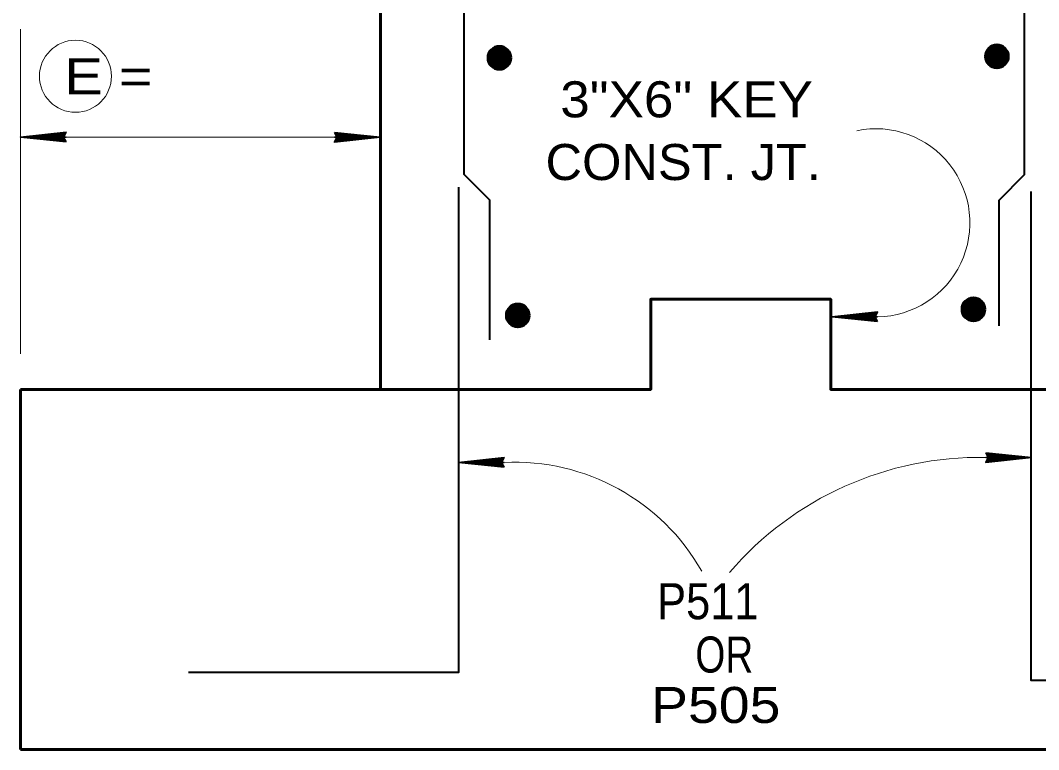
# Model space of a CAD drawing. Extents: x 6.34 to 9.53, y -1.46 to 0.53.
# Drawn here: x 7.7101 to 7.9457, y -0.8062 to -0.6375 of the extents above; entities that cross this region are included whole.
import ezdxf

# ---------------------------------------------------------------- set-up
doc = ezdxf.new("R2010")
doc.units = 0
doc.header["$LTSCALE"] = 0.0033
doc.layers.add('1', color=7, linetype='Continuous', lineweight=40)

msp = doc.modelspace()

# ---------------------------------------------------------------- linework, layer by layer
at = {"layer": '1', "lineweight": 13}
for p, q in [((7.710083, -0.714583), (7.710083, -0.6395)), ((7.710083, -0.6645), (7.7915, -0.6645))]:
    msp.add_line(p, q, dxfattribs=at)
at = {"layer": '1'}
for p, q in [((7.818833, -0.644583), (7.823417, -0.64675)), ((7.819083, -0.645), (7.823, -0.64575)), ((7.819083, -0.645167), (7.823, -0.645917)), ((7.819083, -0.645417), (7.822917, -0.646167)), ((7.819167, -0.644583), (7.823083, -0.64525)), ((7.819167, -0.64475), (7.823083, -0.6455)), ((7.81925, -0.64425), (7.823083, -0.644917)), ((7.821167, -0.645083), (7.8225, -0.644083)), ((7.82325, -0.644917), (7.822, -0.64375)), ((7.933917, -0.64425), (7.9385, -0.646417)), ((7.934083, -0.64525), (7.937917, -0.645917)), ((7.934083, -0.645417), (7.937917, -0.646167)), ((7.934167, -0.644667), (7.938083, -0.645417)), ((7.934167, -0.644833), (7.938083, -0.645583)), ((7.934167, -0.645083), (7.938, -0.645833)), ((7.93425, -0.64425), (7.938167, -0.644917)), ((7.93425, -0.644417), (7.938167, -0.645167)), ((7.934333, -0.643917), (7.938167, -0.644583)), ((7.93625, -0.64475), (7.937583, -0.64375)), ((7.938333, -0.644583), (7.937083, -0.643417)), ((7.818667, -0.647333), (7.8225, -0.648083)), ((7.818667, -0.6475), (7.8225, -0.64825)), ((7.81875, -0.646833), (7.822667, -0.647583)), ((7.81875, -0.647), (7.822583, -0.64775)), ((7.81875, -0.64725), (7.822583, -0.647917)), ((7.818833, -0.646417), (7.82275, -0.647167)), ((7.818917, -0.646), (7.82275, -0.64675)), ((7.818917, -0.646167), (7.82275, -0.646917)), ((7.819, -0.645583), (7.822833, -0.64625)), ((7.819, -0.64575), (7.822833, -0.6465)), ((7.823, -0.64775), (7.81925, -0.648167)), ((7.93375, -0.647), (7.937583, -0.64775)), ((7.93375, -0.647167), (7.937583, -0.647917)), ((7.933833, -0.6465), (7.93775, -0.64725)), ((7.933833, -0.646667), (7.937667, -0.647417)), ((7.933833, -0.646917), (7.937667, -0.647583)), ((7.933917, -0.646083), (7.937833, -0.646833)), ((7.934, -0.645667), (7.937833, -0.646417)), ((7.934, -0.645833), (7.937833, -0.646583)), ((7.938083, -0.647417), (7.934333, -0.647833)), ((7.932917, -0.703083), (7.931667, -0.701917)), ((7.823083, -0.704167), (7.827667, -0.706333)), ((7.823417, -0.704167), (7.827333, -0.704833)), ((7.823417, -0.704333), (7.827333, -0.705083)), ((7.8235, -0.703833), (7.827333, -0.7045)), ((7.825417, -0.704667), (7.82675, -0.703667)), ((7.8275, -0.7045), (7.82625, -0.703333)), ((7.9285, -0.70275), (7.933083, -0.704917)), ((7.928583, -0.704167), (7.932417, -0.704917)), ((7.928583, -0.704333), (7.932417, -0.705083)), ((7.928667, -0.70375), (7.9325, -0.704417)), ((7.928667, -0.703917), (7.9325, -0.704667)), ((7.92875, -0.703167), (7.932667, -0.703917)), ((7.92875, -0.703333), (7.932667, -0.704083)), ((7.92875, -0.703583), (7.932583, -0.704333)), ((7.928833, -0.70275), (7.93275, -0.703417)), ((7.928833, -0.702917), (7.93275, -0.703667)), ((7.928917, -0.702417), (7.93275, -0.703083)), ((7.930833, -0.70325), (7.932167, -0.70225)), ((7.823, -0.706417), (7.826917, -0.707167)), ((7.823, -0.706583), (7.826833, -0.707333)), ((7.823083, -0.706), (7.827, -0.70675)), ((7.823167, -0.705583), (7.827, -0.706333)), ((7.823167, -0.70575), (7.827, -0.7065)), ((7.82325, -0.705167), (7.827083, -0.705833)), ((7.82325, -0.705333), (7.827083, -0.706083)), ((7.823333, -0.704583), (7.82725, -0.705333)), ((7.823333, -0.70475), (7.82725, -0.7055)), ((7.823333, -0.705), (7.827167, -0.70575)), ((7.928333, -0.7055), (7.932167, -0.70625)), ((7.928333, -0.705667), (7.932167, -0.706417)), ((7.928417, -0.705), (7.932333, -0.70575)), ((7.928417, -0.705167), (7.93225, -0.705917)), ((7.928417, -0.705417), (7.93225, -0.706083)), ((7.9285, -0.704583), (7.932417, -0.705333)), ((7.932667, -0.705917), (7.928917, -0.706333)), ((7.822917, -0.706917), (7.82675, -0.707667)), ((7.822917, -0.707083), (7.82675, -0.707833)), ((7.823, -0.706833), (7.826833, -0.7075)), ((7.82725, -0.707333), (7.8235, -0.70775))]:
    msp.add_line(p, q, dxfattribs=at)
at = {"layer": '1', "lineweight": 60}
for p, q in [((7.819083, -0.644583), (7.818917, -0.6475)), ((7.819333, -0.644583), (7.819083, -0.6475)), ((7.8195, -0.644583), (7.819333, -0.647583)), ((7.819667, -0.644583), (7.819417, -0.647583)), ((7.819833, -0.644583), (7.819667, -0.647583)), ((7.820083, -0.644583), (7.819917, -0.647583)), ((7.820333, -0.644583), (7.820083, -0.647583)), ((7.820417, -0.644667), (7.82025, -0.647583)), ((7.820583, -0.644667), (7.820417, -0.647583)), ((7.82075, -0.644667), (7.820583, -0.647583)), ((7.821, -0.644667), (7.82075, -0.647583)), ((7.821167, -0.644667), (7.821, -0.647583)), ((7.821417, -0.64475), (7.821167, -0.647667)), ((7.821667, -0.64475), (7.821417, -0.647667)), ((7.821833, -0.64475), (7.821667, -0.647667)), ((7.821917, -0.64475), (7.82175, -0.647667)), ((7.822083, -0.64475), (7.821917, -0.647667)), ((7.822167, -0.64475), (7.822, -0.647667)), ((7.822417, -0.644833), (7.822167, -0.64775)), ((7.822583, -0.644833), (7.822417, -0.64775)), ((7.82275, -0.644833), (7.8225, -0.64775)), ((7.822917, -0.644833), (7.82275, -0.64775)), ((7.823167, -0.644833), (7.823, -0.64775)), ((7.823417, -0.64675), (7.82325, -0.644917)), ((7.934167, -0.64425), (7.934, -0.647167)), ((7.934417, -0.64425), (7.934167, -0.647167)), ((7.934583, -0.64425), (7.934417, -0.64725)), ((7.93475, -0.64425), (7.9345, -0.64725)), ((7.934917, -0.64425), (7.93475, -0.64725)), ((7.935167, -0.64425), (7.935, -0.64725)), ((7.935417, -0.64425), (7.935167, -0.64725)), ((7.9355, -0.644333), (7.935333, -0.64725)), ((7.935667, -0.644333), (7.9355, -0.64725)), ((7.935833, -0.644333), (7.935667, -0.64725)), ((7.936083, -0.644333), (7.935833, -0.64725)), ((7.93625, -0.644333), (7.936083, -0.64725)), ((7.9365, -0.644417), (7.93625, -0.647333)), ((7.93675, -0.644417), (7.9365, -0.647333)), ((7.936917, -0.644417), (7.93675, -0.647333)), ((7.937, -0.644417), (7.936833, -0.647333)), ((7.937167, -0.644417), (7.937, -0.647333)), ((7.93725, -0.644417), (7.937083, -0.647333)), ((7.9375, -0.6445), (7.93725, -0.647417)), ((7.937667, -0.6445), (7.9375, -0.647417)), ((7.937833, -0.6445), (7.937583, -0.647417)), ((7.938, -0.6445), (7.937833, -0.647417)), ((7.93825, -0.6445), (7.938083, -0.647417)), ((7.9385, -0.646417), (7.938333, -0.644583)), ((7.823417, -0.64675), (7.818667, -0.6475)), ((7.9385, -0.646417), (7.93375, -0.647167)), ((7.823333, -0.704167), (7.823167, -0.707083)), ((7.823583, -0.704167), (7.823333, -0.707083)), ((7.82375, -0.704167), (7.823583, -0.707167)), ((7.823917, -0.704167), (7.823667, -0.707167)), ((7.824083, -0.704167), (7.823917, -0.707167)), ((7.824333, -0.704167), (7.824167, -0.707167)), ((7.824583, -0.704167), (7.824333, -0.707167)), ((7.824667, -0.70425), (7.8245, -0.707167)), ((7.824833, -0.70425), (7.824667, -0.707167)), ((7.825, -0.70425), (7.824833, -0.707167)), ((7.82525, -0.70425), (7.825, -0.707167)), ((7.825417, -0.70425), (7.82525, -0.707167)), ((7.825667, -0.704333), (7.825417, -0.70725)), ((7.825917, -0.704333), (7.825667, -0.70725)), ((7.826083, -0.704333), (7.825917, -0.70725)), ((7.826167, -0.704333), (7.826, -0.70725)), ((7.826333, -0.704333), (7.826167, -0.70725)), ((7.826417, -0.704333), (7.82625, -0.70725)), ((7.92875, -0.70275), (7.928583, -0.705667)), ((7.929, -0.70275), (7.92875, -0.705667)), ((7.929167, -0.70275), (7.929, -0.70575)), ((7.929333, -0.70275), (7.929083, -0.70575)), ((7.9295, -0.70275), (7.929333, -0.70575)), ((7.92975, -0.70275), (7.929583, -0.70575)), ((7.93, -0.70275), (7.92975, -0.70575)), ((7.930083, -0.702833), (7.929917, -0.70575)), ((7.93025, -0.702833), (7.930083, -0.70575)), ((7.930417, -0.702833), (7.93025, -0.70575)), ((7.930667, -0.702833), (7.930417, -0.70575)), ((7.930833, -0.702833), (7.930667, -0.70575)), ((7.931083, -0.702917), (7.930833, -0.705833)), ((7.931333, -0.702917), (7.931083, -0.705833)), ((7.9315, -0.702917), (7.931333, -0.705833)), ((7.931583, -0.702917), (7.931417, -0.705833)), ((7.93175, -0.702917), (7.931583, -0.705833)), ((7.931833, -0.702917), (7.931667, -0.705833)), ((7.932083, -0.703), (7.931833, -0.705917)), ((7.93225, -0.703), (7.932083, -0.705917)), ((7.932417, -0.703), (7.932167, -0.705917)), ((7.932583, -0.703), (7.932417, -0.705917)), ((7.932833, -0.703), (7.932667, -0.705917)), ((7.933083, -0.704917), (7.932917, -0.703083)), ((7.827667, -0.706333), (7.822917, -0.707083)), ((7.826667, -0.704417), (7.826417, -0.707333)), ((7.826833, -0.704417), (7.826667, -0.707333)), ((7.827, -0.704417), (7.82675, -0.707333)), ((7.827167, -0.704417), (7.827, -0.707333)), ((7.827417, -0.704417), (7.82725, -0.707333)), ((7.827667, -0.706333), (7.8275, -0.7045)), ((7.933083, -0.704917), (7.928333, -0.705667)), ((7.710083, -0.806167), (7.710083, -0.722833)), ((8.043417, -0.806167), (7.710083, -0.806167))]:
    msp.add_line(p, q, dxfattribs=at)
at = {"layer": '1', "lineweight": 35}
for p, q in [((7.720417, -0.665333), (7.712583, -0.664333)), ((7.720417, -0.663417), (7.713083, -0.66425)), ((7.720417, -0.663583), (7.713083, -0.664333)), ((7.720417, -0.663667), (7.713083, -0.6645)), ((7.7205, -0.663833), (7.713167, -0.664583)), ((7.783, -0.6635), (7.790833, -0.664417)), ((7.783, -0.6635), (7.790833, -0.664417)), ((7.783, -0.663583), (7.790833, -0.664417)), ((7.783, -0.663667), (7.790833, -0.6645)), ((7.783, -0.663667), (7.790833, -0.664667)), ((7.720667, -0.6645), (7.710083, -0.6645)), ((7.720417, -0.665333), (7.712583, -0.6645)), ((7.720417, -0.6655), (7.712583, -0.664583)), ((7.720417, -0.6655), (7.712583, -0.664583)), ((7.720417, -0.665417), (7.712583, -0.664583)), ((7.78275, -0.6645), (7.793333, -0.6645)), ((7.782917, -0.665167), (7.79025, -0.664417)), ((7.783, -0.665333), (7.790333, -0.6645)), ((7.783, -0.665417), (7.790333, -0.664667)), ((7.783, -0.665583), (7.790333, -0.66475)), ((7.908417, -0.706083), (7.897833, -0.706083)), ((7.908167, -0.706917), (7.900333, -0.705917)), ((7.908167, -0.706917), (7.900333, -0.706083)), ((7.908167, -0.707083), (7.900333, -0.706167)), ((7.908167, -0.707083), (7.900333, -0.706167)), ((7.908167, -0.707), (7.900333, -0.706167)), ((7.908167, -0.705), (7.900833, -0.705833)), ((7.908167, -0.705167), (7.900833, -0.705917)), ((7.908167, -0.70525), (7.900833, -0.706083)), ((7.90825, -0.705417), (7.900917, -0.706167)), ((7.82175, -0.740583), (7.813917, -0.739583)), ((7.82175, -0.738667), (7.814417, -0.7395)), ((7.82175, -0.738833), (7.814417, -0.739583)), ((7.82175, -0.738917), (7.814417, -0.73975)), ((7.821833, -0.739083), (7.8145, -0.739833)), ((7.933417, -0.738583), (7.944, -0.738583)), ((7.933583, -0.73925), (7.940917, -0.7385)), ((7.933667, -0.737583), (7.9415, -0.7385)), ((7.933667, -0.737583), (7.9415, -0.7385)), ((7.933667, -0.737667), (7.9415, -0.7385)), ((7.933667, -0.73775), (7.9415, -0.738583)), ((7.933667, -0.73775), (7.9415, -0.73875)), ((7.933667, -0.739417), (7.941, -0.738583)), ((7.933667, -0.7395), (7.941, -0.73875)), ((7.933667, -0.739667), (7.941, -0.738833)), ((7.822, -0.73975), (7.811417, -0.73975)), ((7.82175, -0.740583), (7.813917, -0.73975)), ((7.82175, -0.74075), (7.813917, -0.739833)), ((7.82175, -0.74075), (7.813917, -0.739833)), ((7.82175, -0.740667), (7.813917, -0.739833))]:
    msp.add_line(p, q, dxfattribs=at)
at = {"layer": '1', "lineweight": 60}
for points in [[(7.710083, -0.722833), (7.793417, -0.722833), (7.793417, -0.3895), (7.960083, -0.3895), (7.960083, -0.722833), (8.043417, -0.722833)], [(7.81825, -0.64625), (7.823417, -0.645583), (7.818833, -0.644583)], [(7.8225, -0.64825), (7.8225, -0.644083), (7.820833, -0.64875), (7.821333, -0.643583), (7.81925, -0.648167), (7.82, -0.643667), (7.821583, -0.648667), (7.818417, -0.645333), (7.82325, -0.644917), (7.82, -0.648583), (7.822, -0.64375), (7.818833, -0.644583), (7.818667, -0.6475)], [(7.81925, -0.648167), (7.82075, -0.645917), (7.818583, -0.645), (7.820583, -0.643583), (7.82075, -0.645833), (7.822417, -0.648167), (7.818417, -0.645833), (7.821167, -0.645083)], [(7.822, -0.64375), (7.82075, -0.645917), (7.823, -0.64775)], [(7.933333, -0.645917), (7.9385, -0.64525), (7.933917, -0.64425)], [(7.937583, -0.647917), (7.937583, -0.64375), (7.935917, -0.648417), (7.936417, -0.64325), (7.934333, -0.647833), (7.935083, -0.643333), (7.936667, -0.648333), (7.9335, -0.645), (7.938333, -0.644583), (7.935083, -0.64825), (7.937083, -0.643417), (7.933917, -0.64425), (7.93375, -0.647167)], [(7.934333, -0.647833), (7.935833, -0.645583), (7.933667, -0.644667), (7.935667, -0.64325), (7.935833, -0.6455), (7.9375, -0.647833), (7.9335, -0.6455), (7.93625, -0.64475)], [(7.937083, -0.643417), (7.935833, -0.645583), (7.938083, -0.647417)], [(7.793417, -0.722833), (7.855917, -0.722833), (7.855917, -0.702), (7.897583, -0.702), (7.897583, -0.722833), (7.960083, -0.722833)], [(7.932167, -0.706417), (7.932167, -0.70225), (7.9305, -0.706917), (7.931, -0.70175), (7.928917, -0.706333), (7.929667, -0.701833), (7.93125, -0.706833), (7.928083, -0.7035), (7.932917, -0.703083), (7.929667, -0.70675), (7.931667, -0.701917), (7.9285, -0.70275), (7.928333, -0.705667)], [(7.928917, -0.706333), (7.930417, -0.704083), (7.92825, -0.703167), (7.93025, -0.70175), (7.930417, -0.704), (7.932083, -0.706333), (7.928083, -0.704), (7.930833, -0.70325)], [(7.931667, -0.701917), (7.930417, -0.704083), (7.932667, -0.705917)], [(7.8225, -0.705833), (7.827667, -0.705167), (7.823083, -0.704167)], [(7.82675, -0.707833), (7.82675, -0.703667), (7.825083, -0.708333), (7.825583, -0.703167), (7.8235, -0.70775), (7.82425, -0.70325), (7.825833, -0.70825), (7.822667, -0.704917), (7.8275, -0.7045), (7.82425, -0.708167), (7.82625, -0.703333), (7.823083, -0.704167), (7.822917, -0.707083)], [(7.8235, -0.70775), (7.825, -0.7055), (7.822833, -0.704583), (7.824833, -0.703167), (7.825, -0.705417), (7.826667, -0.70775), (7.822667, -0.705417), (7.825417, -0.704667)], [(7.82625, -0.703333), (7.825, -0.7055), (7.82725, -0.707333)], [(7.927917, -0.704417), (7.933083, -0.70375), (7.9285, -0.70275)]]:
    msp.add_lwpolyline(points, dxfattribs=at)
at = {"layer": '1'}
for points in [[(7.818583, -0.410167), (7.818583, -0.458833), (7.812667, -0.46475), (7.812667, -0.673083), (7.818583, -0.679), (7.818583, -0.711417)], [(7.9365, -0.708167), (7.9365, -0.679083), (7.942417, -0.673167), (7.942417, -0.464833), (7.9365, -0.458917), (7.9365, -0.410333)], [(7.818667, -0.6475), (7.82075, -0.64875), (7.8225, -0.64825), (7.823417, -0.64675)], [(7.93375, -0.647167), (7.935833, -0.648417), (7.937583, -0.647917), (7.9385, -0.646417)], [(7.749, -0.78825), (7.8115, -0.78825), (7.8115, -0.676083)], [(7.943833, -0.677083), (7.943833, -0.790083), (8.006333, -0.790083)], [(7.822917, -0.707083), (7.825, -0.708333), (7.82675, -0.707833), (7.827667, -0.706333)], [(7.928333, -0.705667), (7.930417, -0.706917), (7.932167, -0.706417), (7.933083, -0.704917)]]:
    msp.add_lwpolyline(points, dxfattribs=at)
at = {"layer": '1', "lineweight": 35}
for points in [[(7.720667, -0.665583), (7.710083, -0.6645), (7.720667, -0.663333), (7.720083, -0.6645)], [(7.719917, -0.664583), (7.71525, -0.664667), (7.71525, -0.664583), (7.716167, -0.664583), (7.719917, -0.664667), (7.716917, -0.66475), (7.720083, -0.664833), (7.717833, -0.664917), (7.720083, -0.665), (7.716583, -0.66475), (7.711917, -0.664583), (7.712833, -0.664333), (7.711583, -0.664333), (7.719917, -0.664333), (7.7175, -0.664167), (7.720083, -0.664167), (7.71475, -0.664583), (7.720083, -0.663917)], [(7.78275, -0.663417), (7.793333, -0.6645), (7.78275, -0.665667), (7.783333, -0.6645)], [(7.7835, -0.664417), (7.788167, -0.664333), (7.788167, -0.664417), (7.78725, -0.664417), (7.7835, -0.664333), (7.7865, -0.66425), (7.783333, -0.664167), (7.785583, -0.664083), (7.783333, -0.664), (7.786833, -0.66425), (7.7915, -0.664417), (7.790583, -0.664667), (7.791833, -0.664667), (7.7835, -0.664667), (7.785917, -0.664833), (7.783333, -0.664833), (7.788667, -0.664417), (7.783333, -0.665083)], [(7.908417, -0.707167), (7.897833, -0.706083), (7.908417, -0.704917), (7.907833, -0.706083)], [(7.907667, -0.706167), (7.903, -0.70625), (7.903, -0.706167), (7.903917, -0.706167), (7.907667, -0.70625), (7.904667, -0.706333), (7.907833, -0.706417), (7.905583, -0.7065), (7.907833, -0.706583), (7.904333, -0.706333), (7.899667, -0.706167), (7.900583, -0.705917), (7.899333, -0.705917), (7.907667, -0.705917), (7.90525, -0.70575), (7.907833, -0.70575), (7.9025, -0.706167), (7.907833, -0.7055)], [(7.822, -0.740833), (7.811417, -0.73975), (7.822, -0.738583), (7.821417, -0.73975)], [(7.82125, -0.739833), (7.816583, -0.739917), (7.816583, -0.739833), (7.8175, -0.739833), (7.82125, -0.739917), (7.81825, -0.74), (7.821417, -0.740083), (7.819167, -0.740167), (7.821417, -0.74025), (7.817917, -0.74), (7.81325, -0.739833), (7.814167, -0.739583), (7.812917, -0.739583), (7.82125, -0.739583), (7.818833, -0.739417), (7.821417, -0.739417), (7.816083, -0.739833), (7.821417, -0.739167)], [(7.933417, -0.7375), (7.944, -0.738583), (7.933417, -0.73975), (7.934, -0.738583)], [(7.934167, -0.7385), (7.938833, -0.738417), (7.938833, -0.7385), (7.937917, -0.7385), (7.934167, -0.738417), (7.937167, -0.738333), (7.934, -0.73825), (7.93625, -0.738167), (7.934, -0.738083), (7.9375, -0.738333), (7.942167, -0.7385), (7.94125, -0.73875), (7.9425, -0.73875), (7.934167, -0.73875), (7.936583, -0.738917), (7.934, -0.738917), (7.939333, -0.7385), (7.934, -0.739167)]]:
    msp.add_lwpolyline(points, close=True, dxfattribs=at)
for points in [[(7.719917, -0.664583), (7.720333, -0.665333), (7.720083, -0.665083), (7.719917, -0.66475), (7.719667, -0.664833), (7.719833, -0.665167), (7.72, -0.664417), (7.720167, -0.663917), (7.720417, -0.6635)], [(7.7835, -0.664417), (7.783083, -0.663667), (7.783333, -0.663917), (7.7835, -0.66425), (7.78375, -0.664167), (7.783583, -0.663833), (7.783417, -0.664583), (7.78325, -0.665083), (7.783, -0.6655)], [(7.907667, -0.706167), (7.908083, -0.706917), (7.907833, -0.706667), (7.907667, -0.706333), (7.907417, -0.706417), (7.907583, -0.70675), (7.90775, -0.706), (7.907917, -0.7055), (7.908167, -0.705083)], [(7.82125, -0.739833), (7.821667, -0.740583), (7.821417, -0.740333), (7.82125, -0.74), (7.821, -0.740083), (7.821167, -0.740417), (7.821333, -0.739667), (7.8215, -0.739167), (7.82175, -0.73875)], [(7.934167, -0.7385), (7.93375, -0.73775), (7.934, -0.738), (7.934167, -0.738333), (7.934417, -0.73825), (7.93425, -0.737917), (7.934083, -0.738667), (7.933917, -0.739167), (7.933667, -0.739583)]]:
    msp.add_lwpolyline(points, dxfattribs=at)
at = {"layer": '1', "lineweight": 13}
msp.add_circle((7.722833, -0.650417), 0.008333, dxfattribs=at)
at = {"layer": '1', "lineweight": 60}
for centre in [(7.820917, -0.64615), (7.936, -0.645817), (7.930583, -0.704317), (7.825167, -0.705733)]:
    msp.add_circle(centre, 0.00264, dxfattribs=at)
at = {"layer": '1', "lineweight": 13}
for centre, radius, start, end in [((7.907995, -0.684318), 0.02177, 271.10937, 101.69263), ((7.824451, -0.789462), 0.049773, 29.5481, 92.8223), ((7.932011, -0.814772), 0.076202, 88.94317, 139.38493)]:
    msp.add_arc(centre, radius, start, end, dxfattribs=at)

# ---------------------------------------------------------------- texts
at = {"layer": '1'}
for s, height, width, p in [('E =      ', 0.008334, 1.2, (7.72025, -0.654583)), ('3"X6" KEY', 0.008334, 1.1, (7.835, -0.659917)), ('CONST. JT. ', 0.008334, 1.05, (7.831583, -0.674417)), ('P511', 0.008333, 0.9, (7.857417, -0.776)), ('OR', 0.008333, 0.8, (7.86625, -0.788333)), ('P505', 0.008333, 1.15, (7.856, -0.8))]:
    msp.add_text(s, height=height, dxfattribs=dict(at, width=width)).set_placement(p)

doc.saveas('drawing.dxf')
